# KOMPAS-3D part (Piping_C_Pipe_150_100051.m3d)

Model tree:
1. Plane XY
2. Plane ZX
3. Plane ZY
4. X Axis
5. Y Axis
6. Z Axis
7. Origin
8. Path  (labels: Тройник Dy 150; Труба Dy 150; Задвижка Dy 150)
9. Plane of section
10. Section of pipe
11. Pipe
     Толщина стенки 1 = 1

Referenced files in C:\Program Files\ASCON\KOMPAS-3D V10\Libs\Piping\Models\Tanks\: Tanks.a3d
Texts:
  Pipe Dn 150
  Steel ASTM A295
  Three Point Plane
  Plane at Angle
  Line and Point Plane
  Axis through Two Vertices
  Axis of Feature
  Axis of Conical Surface
  Axis through Edge
  Приклеить элемент выдавливания
  Приклеить элемент вращения
  Приклеить кинематический элемент
  Приклеить элемент по сечениям
  Trim by Surface
  Trim by Sketch
  Feature with No History
  Intersection Axis of Two Planes
  Two Line Plane
  Line and Face Plane
  Bend by line
  Hole in sheet body
  Cut in sheet body
  Point in CM
  Linear Dimension from Line to Point
  Surface Finish Symbol
  Geometric Tolerance Symbol
  Текст на чертеже
  Линия-выноска #1
  Линия-выноска #2
  Линия-выноска #3
  Отклонения формы и база
  Марка координационной оси
  Марка/позиционное обозначение с линией-выноской
  Марка/позиционное обозначение на линии
  Марка/позиционное обозначение без линии-выноски
  Тройник Dy 150
  Труба Dy 150
  Задвижка Dy 150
